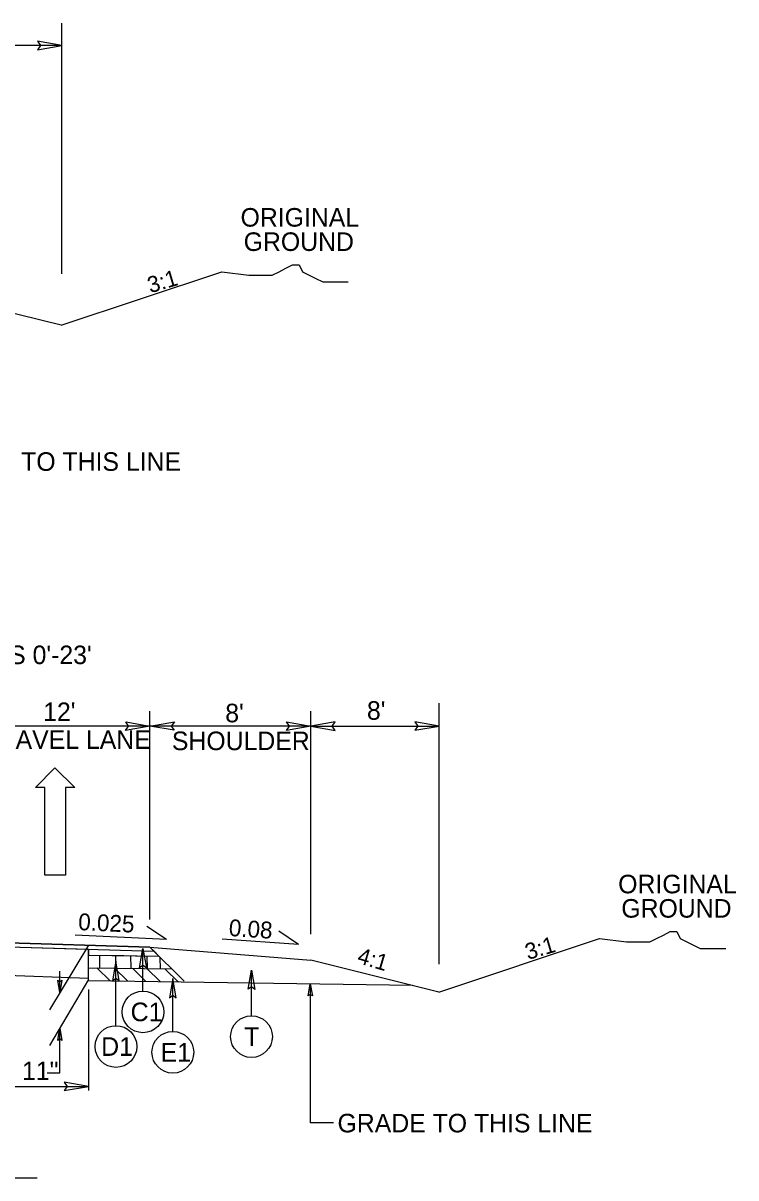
# Model space of a CAD drawing. Extents: x 2176156 to 2177167, y 76401 to 76644.
# Drawn here: x 2176334.6 to 2176378.9, y 76546.5 to 76618.2 of the extents above; entities that cross this region are included whole.
import ezdxf

# ---------------------------------------------------------------- set-up
doc = ezdxf.new("R2010")
doc.units = 0
for name, color, linetype in [('Exist Building', 7, 'Continuous'), ('Exist Roads Curbs', 7, 'Continuous'), ('Exist Roads EOP Other', 7, 'Continuous'), ('Exist Roads Soil', 7, 'Continuous'), ('Exist Structure Minor Culvert Topo', 7, 'Continuous'), ('Exist Structure Minor Drop Inlet', 7, 'Continuous'), ('Exist Utilities Other Pole CELL', 7, 'Continuous'), ('Model Boundary Lines Text', 7, 'Continuous'), ('Old_Level_1', 7, 'Continuous'), ('Old_Level_3', 7, 'Continuous'), ('Prop North Arrow NAD83 for Plan Sheets CELL', 7, 'Continuous'), ('Sheet Plan CELL', 7, 'Continuous')]:
    doc.layers.add(name, color=color, linetype=linetype)

msp = doc.modelspace()

# ---------------------------------------------------------------- linework, layer by layer
at = {"layer": 'Exist Building'}
for p, q in [((2176338.626, 76558.715), (2176338.626, 76560.666)), ((2176358.771, 76558.415), (2176338.626, 76558.715))]:
    msp.add_line(p, q, dxfattribs=at)
at = {"layer": 'Exist Roads Curbs'}
for p, q in [((2176322.436, 76561.171), (2176342.704, 76560.539)), ((2176330.444, 76561.171), (2176342.444, 76560.797)), ((2176342.444, 76560.797), (2176330.444, 76561.171)), ((2176330.444, 76560.921), (2176338.626, 76560.666)), ((2176342.704, 76560.539), (2176342.444, 76560.797))]:
    msp.add_line(p, q, dxfattribs=at)
for points in [[(2176346.917, 76602.777), (2176348.587, 76602.569), (2176349.005, 76602.569), (2176349.632, 76602.569), (2176350.05, 76602.569), (2176350.468, 76602.777), (2176350.885, 76602.987), (2176351.303, 76603.196), (2176351.721, 76603.196), (2176351.93, 76602.777), (2176352.348, 76602.569), (2176352.766, 76602.359), (2176353.183, 76602.151), (2176353.601, 76602.151), (2176354.019, 76602.151), (2176354.436, 76602.151), (2176354.775, 76602.151)], [(2176370.396, 76561.342), (2176372.067, 76561.135), (2176372.484, 76561.135), (2176373.112, 76561.135), (2176373.529, 76561.135), (2176373.947, 76561.342), (2176374.365, 76561.552), (2176374.782, 76561.762), (2176375.2, 76561.762), (2176375.41, 76561.342), (2176375.827, 76561.135), (2176376.245, 76560.925), (2176376.663, 76560.717), (2176377.08, 76560.717), (2176377.498, 76560.717), (2176377.916, 76560.717), (2176378.255, 76560.717)], [(2176338.626, 76560.666), (2176338.626, 76560.308), (2176340.814, 76560.276), (2176341.646, 76560.263), (2176343.001, 76560.243), (2176342.704, 76560.539)]]:
    msp.add_lwpolyline(points, dxfattribs=at)
at = {"layer": 'Exist Roads EOP Other'}
for p, q in [((2176336.917, 76599.444), (2176346.917, 76602.777)), ((2176336.917, 76599.444), (2176328.965, 76601.431)), ((2176342.444, 76560.797), (2176352.444, 76559.997)), ((2176360.396, 76558.009), (2176370.396, 76561.342)), ((2176360.396, 76558.009), (2176352.444, 76559.997))]:
    msp.add_line(p, q, dxfattribs=at)
at = {"layer": 'Exist Roads Soil'}
for p, q in [((2176342.444, 76560.797), (2176344.561, 76558.693)), ((2176338.626, 76560.308), (2176343.001, 76560.243)), ((2176338.626, 76559.521), (2176343.805, 76559.444))]:
    msp.add_line(p, q, dxfattribs=at)
at = {"layer": 'Exist Structure Minor Drop Inlet'}
for p, q in [((2176335.33, 76570.711), (2176336.533, 76571.933)), ((2176336.533, 76571.933), (2176337.774, 76570.711)), ((2176335.912, 76570.711), (2176335.33, 76570.711)), ((2176335.912, 76565.279), (2176335.912, 76570.711)), ((2176337.774, 76570.711), (2176337.192, 76570.711)), ((2176337.192, 76570.711), (2176337.192, 76565.279)), ((2176337.192, 76565.279), (2176335.912, 76565.279))]:
    msp.add_line(p, q, dxfattribs=at)
at = {"layer": 'Exist Utilities Other Pole CELL'}
for p, q in [((2176343.481, 76561.283), (2176342.241, 76562.078)), ((2176343.481, 76561.283), (2176337.801, 76561.548)), ((2176351.672, 76560.973), (2176350.447, 76561.792)), ((2176351.672, 76560.973), (2176346.926, 76561.287))]:
    msp.add_line(p, q, dxfattribs=at)
at = {"layer": 'Model Boundary Lines Text'}
for p, q in [((2176339.33, 76559.511), (2176339.319, 76560.298)), ((2176340.328, 76559.496), (2176340.316, 76560.283)), ((2176341.268, 76559.482), (2176341.257, 76560.269)), ((2176342.286, 76559.467), (2176342.275, 76560.254)), ((2176343.099, 76559.455), (2176343.089, 76560.156)), ((2176339.984, 76558.685), (2176339.148, 76559.503)), ((2176341.074, 76558.676), (2176340.238, 76559.495)), ((2176342.193, 76558.673), (2176341.357, 76559.491)), ((2176343.086, 76558.654), (2176342.259, 76559.464)), ((2176344.227, 76558.622), (2176343.391, 76559.44)), ((2176308.108, 76546.457), (2176335.43, 76546.457))]:
    msp.add_line(p, q, dxfattribs=at)
at = {"layer": 'Old_Level_1'}
for points in [[(2176335.455, 76616.572), (2176336.965, 76616.832), (2176335.447, 76617.101), (2176335.64, 76616.832)], [(2176340.934, 76574.795), (2176342.444, 76574.535), (2176340.926, 76574.267), (2176341.119, 76574.535)], [(2176343.954, 76574.275), (2176342.444, 76574.535), (2176343.962, 76574.803), (2176343.769, 76574.535)], [(2176350.934, 76574.795), (2176352.444, 76574.535), (2176350.926, 76574.267), (2176351.119, 76574.535)], [(2176353.954, 76574.795), (2176352.444, 76574.535), (2176353.962, 76574.267), (2176353.769, 76574.535)], [(2176358.922, 76574.275), (2176360.431, 76574.535), (2176358.913, 76574.803), (2176359.106, 76574.535)], [(2176336.97, 76558.738), (2176336.838, 76557.984), (2176336.706, 76558.743), (2176336.84, 76558.646)], [(2176352.275, 76557.77), (2176352.405, 76558.525), (2176352.54, 76557.766), (2176352.405, 76557.862)], [(2176336.706, 76555.005), (2176336.838, 76555.759), (2176336.97, 76555), (2176336.836, 76555.096)], [(2176337.117, 76551.883), (2176338.626, 76552.143), (2176337.108, 76552.411), (2176337.301, 76552.143)]]:
    msp.add_lwpolyline(points, close=True, dxfattribs=at)
at = {"layer": 'Old_Level_3'}
for p, q in [((2176336.965, 76602.644), (2176336.965, 76618.228)), ((2176336.965, 76616.832), (2176322.965, 76616.832)), ((2176360.431, 76559.738), (2176360.431, 76575.968)), ((2176342.444, 76562.523), (2176342.444, 76575.463)), ((2176352.444, 76561.595), (2176352.444, 76575.463)), ((2176342.444, 76574.535), (2176330.444, 76574.535)), ((2176352.444, 76574.535), (2176342.444, 76574.535)), ((2176352.444, 76574.535), (2176360.431, 76574.535)), ((2176338.626, 76560.916), (2176336.201, 76556.908)), ((2176336.838, 76557.984), (2176336.838, 76559.312)), ((2176338.626, 76558.778), (2176336.201, 76554.684)), ((2176352.405, 76558.525), (2176352.405, 76549.889)), ((2176338.626, 76558.17), (2176338.626, 76551.889)), ((2176336.838, 76552.983), (2176336.838, 76555.759)), ((2176336.058, 76552.983), (2176336.838, 76552.983)), ((2176312.317, 76552.143), (2176338.626, 76552.143)), ((2176353.86, 76549.889), (2176352.405, 76549.889))]:
    msp.add_line(p, q, dxfattribs=at)
at = {"layer": 'Prop North Arrow NAD83 for Plan Sheets CELL'}
for p, q in [((2176342.01, 76558.07), (2176342.01, 76560.72)), ((2176340.329, 76555.918), (2176340.329, 76559.918)), ((2176348.758, 76556.536), (2176348.758, 76559.378)), ((2176343.867, 76555.562), (2176343.867, 76558.858))]:
    msp.add_line(p, q, dxfattribs=at)
for points in [[(2176341.803, 76559.52), (2176342.01, 76560.72), (2176342.223, 76559.513), (2176342.01, 76559.667)], [(2176340.536, 76558.718), (2176340.329, 76559.918), (2176340.116, 76558.711), (2176340.329, 76558.865)], [(2176348.551, 76558.178), (2176348.758, 76559.378), (2176348.971, 76558.172), (2176348.758, 76558.325)], [(2176344.073, 76557.658), (2176343.867, 76558.858), (2176343.653, 76557.651), (2176343.867, 76557.805)]]:
    msp.add_lwpolyline(points, close=True, dxfattribs=at)
for centre in [(2176342.01, 76556.774), (2176348.758, 76555.24), (2176340.329, 76554.622), (2176343.867, 76554.266)]:
    msp.add_circle(centre, 1.296, dxfattribs=at)
at = {"layer": 'Sheet Plan CELL'}
msp.add_line((2176338.626, 76558.851), (2176321.769, 76559.462), dxfattribs=at)

# ---------------------------------------------------------------- texts
at = {"layer": 'Exist Roads Curbs'}
for s, rotation, p in [('3:1', 16.46494, (2176342.463, 76601.431)), ('3:1', 16.46494, (2176365.943, 76559.997)), ('4:1', 343.53506, (2176355.272, 76559.83))]:
    msp.add_text(s, height=1.0064, rotation=rotation, dxfattribs=at).set_placement(p)
at = {"layer": 'Exist Structure Minor Culvert Topo'}
for s, height, p in [('ORIGINAL', 1.1533, (2176348.077, 76605.579)), ('GROUND', 1.1533, (2176348.271, 76604.067)), ('GRADE TO THIS LINE', 1.15334, (2176328.523, 76590.401)), ("VARIES 0'-23'", 1.15334, (2176329.062, 76578.388)), ("12'", 1.1533, (2176335.804, 76574.851)), ("8' ", 1.1533, (2176347.126, 76574.773)), ("8'", 1.1533, (2176355.935, 76574.93)), ('TRAVEL LANE', 1.15334, (2176332.035, 76573.121)), ('SHOULDER', 1.1533, (2176343.807, 76573.043)), ('ORIGINAL', 1.1533, (2176371.556, 76564.144)), ('GROUND', 1.1533, (2176371.75, 76562.632)), ('GRADE TO THIS LINE', 1.15334, (2176354.105, 76549.285))]:
    msp.add_text(s, height=height, dxfattribs=at).set_placement(p)
at = {"layer": 'Exist Utilities Other Pole CELL'}
for s, rotation, p in [('0.025', 357.3324, (2176337.967, 76561.862)), ('0.08', 356.21988, (2176347.322, 76561.497))]:
    msp.add_text(s, height=1.0429, rotation=rotation, dxfattribs=at).set_placement(p)
at = {"layer": 'Prop North Arrow NAD83 for Plan Sheets CELL'}
for s, rotation, p in [('C1', 0.00026, (2176341.241, 76556.194)), ('T', 359.99974, (2176348.301, 76554.66)), ('D1', 359.99974, (2176339.408, 76554.042)), ('E1', 359.99974, (2176343.103, 76553.686))]:
    msp.add_text(s, height=1.16, rotation=rotation, dxfattribs=at).set_placement(p)
msp.add_text('11"', height=1.1533, dxfattribs=at).set_placement((2176334.492, 76552.533))

doc.saveas('drawing.dxf')
